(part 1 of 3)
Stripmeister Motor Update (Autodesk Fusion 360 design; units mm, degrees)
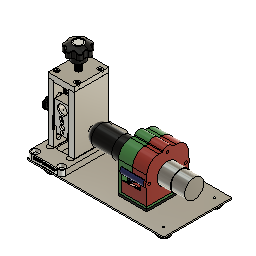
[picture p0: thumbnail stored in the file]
sketch "Sketch1" plane through (0, 0, 0) normal (0, 0, 1) x axis (1, 0, 0)
  line L1 (-38.1, -74.8109) -> (38.1, -74.8109)
  line L2 (-38.1, 74.8109) -> (-38.1, -74.8109)
  line L3 (38.1, 74.8109) -> (-38.1, 74.8109)
  line L4 (38.1, -74.8109) -> (38.1, 74.8109)
  line L5 (-38.1, 74.8109) -> (38.1, -74.8109)
  line L6 (38.1, 74.8109) -> (-38.1, -74.8109)
  line L7 (0, -74.8109) -> (0, 74.8109)
  line L8 (22.225, -74.8109) -> (22.225, 74.8109)
  line L9 (22.225, 0) -> (0, 0)
  line L10 (15.621, -39.4335) -> (15.621, 39.4335)
  line L11 (28.829, 39.4335) -> (28.829, -39.4335)
  line L12 (22.225, -46.0375) -> (22.225, 46.0375)
  line L13 (16.6687, -29.3687) -> (16.6688, 29.3687)
  line L14 (27.7813, 29.3687) -> (27.7813, -29.3688)
  line L15 (22.225, -34.925) -> (22.225, 34.925)
  line L16 (-28.829, 39.4335) -> (-28.829, -39.4335)
  line L17 (-27.7813, 29.3688) -> (-27.7813, -29.3688)
  line L18 (-16.6687, -29.3687) -> (-16.6688, 29.3687)
  line L19 (-15.621, -39.4335) -> (-15.621, 39.4335)
  line L20 (-12.7, 4.1513) -> (12.7, 4.1513)
  line L21 (-12.7, -37.5047) -> (-12.7, 4.1513)
  line L22 (12.7, -37.5047) -> (-12.7, -37.5047)
  line L23 (12.7, 4.1513) -> (12.7, -37.5047)
  line L24 (-12.7, -37.5047) -> (12.7, 4.1513)
  line L25 (12.7, -37.5047) -> (-12.7, 4.1513)
  line L26 (5.08, 10.8982) -> (0, 10.8982)
  line L27 (-3.175, 8.5169) -> (3.175, 8.5169)
  line L28 (-6.35, 18.0419) -> (-6.35, 11.6919)
  line L29 (3.175, 21.2169) -> (-3.175, 21.2169)
  line L30 (6.35, 11.6919) -> (6.35, 18.0419)
  line L31 (-6.35, 21.2169) -> (6.35, 8.5169)
  line L32 (6.35, 21.2169) -> (-6.35, 8.5169)
  circle C1 centre (22.225, 25.4) radius 3.9687
  circle C2 centre (22.225, -25.4) radius 3.9687
  circle C3 centre (-22.225, 25.4) radius 3.9687
  circle C4 centre (-22.225, -25.4) radius 3.9687
  arc A1 centre (22.225, -39.4335) radius 6.604 clockwise from (28.829, -39.4335) to (15.621, -39.4335)
  arc A2 centre (22.225, 39.4335) radius 6.604 clockwise from (15.621, 39.4335) to (28.829, 39.4335)
  arc A3 centre (22.225, -29.3688) radius 5.5563 clockwise from (27.7813, -29.3688) to (16.6687, -29.3687)
  arc A4 centre (22.225, 29.3687) radius 5.5563 clockwise from (16.6688, 29.3687) to (27.7813, 29.3687)
  arc A5 centre (-22.225, 39.4335) radius 6.604 clockwise from (-28.829, 39.4335) to (-15.621, 39.4335)
  arc A6 centre (-22.225, 29.3687) radius 5.5562 clockwise from (-27.7813, 29.3688) to (-16.6688, 29.3687)
  arc A7 centre (-22.225, -39.4335) radius 6.604 clockwise from (-15.621, -39.4335) to (-28.829, -39.4335)
  arc A8 centre (-22.225, -29.3688) radius 5.5562 clockwise from (-16.6687, -29.3687) to (-27.7813, -29.3688)
  circle C5 centre (-22.225, -25.4) radius 3.9687
  circle C6 centre (-22.225, 25.4) radius 3.9687
  circle C7 centre (28.575, 65.2859) radius 4.7625
  circle C8 centre (-28.575, 65.2859) radius 4.7625
  circle C9 centre (28.575, -65.2859) radius 3.9687
  circle C10 centre (-28.575, -65.2859) radius 3.9687
  circle C11 centre (0, 14.8669) radius 3.9688
  arc A9 centre (3.175, 11.6919) radius 3.175 clockwise from (6.35, 11.6919) to (3.175, 8.5169)
  arc A10 centre (-3.175, 11.6919) radius 3.175 clockwise from (-3.175, 8.5169) to (-6.35, 11.6919)
  arc A11 centre (-3.175, 18.0419) radius 3.175 clockwise from (-6.35, 18.0419) to (-3.175, 21.2169)
  arc A12 centre (3.175, 18.0419) radius 3.175 clockwise from (3.175, 21.2169) to (6.35, 18.0419)
  circle C12 centre (0, 62.4919) radius 3.9687
  point P6 (0, 0)
  point P1 (0, 0)
  point P7 (0, 74.8109)
  point P8 (0, -74.8109)
  point P9 (22.225, 74.8109)
  point P10 (22.225, -74.8109)
  point P11 (22.225, 25.4)
  point P12 (22.225, -25.4)
  point P13 (0, 0)
  point P14 (22.225, 0)
  point P23 (22.225, 46.0375)
  point P24 (22.225, -46.0375)
  point P31 (22.225, 34.925)
  point P32 (22.225, -34.925)
  point P17 (15.621, 39.4335)
  point P35 (-15.621, 39.4335)
  point P18 (15.621, -39.4335)
  point P42 (-15.621, -39.4335)
  point P19 (28.829, -39.4335)
  point P36 (-28.829, -39.4335)
  point P20 (28.829, 39.4335)
  point P34 (-28.829, 39.4335)
  point P25 (16.6688, 29.3687)
  point P40 (-16.6688, 29.3687)
  point P26 (16.6687, -29.3687)
  point P41 (-16.6687, -29.3687)
  point P27 (27.7813, -29.3688)
  point P37 (-27.7813, -29.3688)
  point P28 (27.7813, 29.3687)
  point P38 (-27.7813, 29.3688)
  point P51 (0, -16.6767)
  point P56 (0, 10.8982)
  point P58 (0, 14.8669)
  point P63 (0, 14.8669)
  point P59 (6.35, 8.5169)
  point P60 (-6.35, 8.5169)
  point P61 (-6.35, 21.2169)
  point P62 (6.35, 21.2169)
  point P76 (0, 62.4919)
  point P4 (-38.1, 74.8109)
  point P5 (38.1, 74.8109)
  point P3 (-38.1, -74.8109)
  point P49 (-12.7, -37.5047)
  point P50 (12.7, -37.5047)
  point P48 (-12.7, 4.1513)
  point P54 (28.575, -65.2859)
  point P52 (28.575, 65.2859)
  horizontal L1
  perpendicular L1 L2
  parallel L1 L3
  parallel L2 L4
  coincident L5 P6
  coincident L6 P6
  coincident P1 P6
  midpoint L3 P7
  midpoint L1 P8
  coincident L3 P9
  coincident L1 P10
  perpendicular L1 L8
  coincident L8 P11
  coincident L8 P12
  coincident P1 P13
  midpoint L8 P14
  symmetric L7 C1 C3
  symmetric L7 C2 C4
  tangent L10 A1
  tangent A1 L11
  parallel L10 L11
  tangent L11 A2
  tangent L10 A2
  midpoint A2 P23
  midpoint A1 P24
  coincident L8 P24
  parallel L8 L12
  midpoint P14 L12
  tangent L13 A3
  tangent A3 L14
  parallel L13 L14
  tangent L14 A4
  tangent L13 A4
  midpoint A4 P31
  midpoint A3 P32
  parallel L12 L15
  coincident L12 P31
  midpoint P14 L15
  symmetric L7 C1 C6
  symmetric L7 C2 C5
  symmetric L7 P17 P35
  symmetric L7 P18 P42
  symmetric L7 P19 P36
  symmetric L7 P20 P34
  symmetric L7 A1 A7
  symmetric L7 A2 A5
  symmetric L7 P25 P40
  symmetric L7 P26 P41
  symmetric L7 P27 P37
  symmetric L7 P28 P38
  symmetric L7 A3 A8
  symmetric L7 A4 A6
  horizontal L20
  perpendicular L20 L21
  parallel L20 L22
  parallel L21 L23
  coincident L24 P51
  coincident L25 P51
  coincident L7 P51
  symmetric L7 C7 C8
  symmetric L7 C9 C10
  coincident L7 P56
  perpendicular L7 L26
  coincident L7 P58
  tangent L26 C11
  horizontal L27
  perpendicular L27 L28
  parallel L27 L29
  parallel L28 L30
  coincident L31 P63
  coincident L32 P63
  coincident P58 P63
  coincident P59 L30
  coincident P59 L27
  tangent L30 A9
  tangent L27 A9
  coincident P60 L27
  coincident P60 L28
  tangent L27 A10
  tangent L28 A10
  equal A9 A10
  coincident P61 L28
  coincident P61 L29
  tangent L28 A11
  tangent L29 A11
  equal A9 A11
  coincident P62 L29
  coincident P62 L30
  tangent L29 A12
  tangent L30 A12
  equal A9 A12
  coincident L7 P76
  dimension "d1" distance P4 P5 = 76.2
  dimension "d2" distance P3 P4 = 149.6219 (= "5 57/64")
  dimension "d3" diameter C1 = 7.9375 (= "( 5 / 16 ) * 1 in")
  dimension "d4" diameter C2 = 7.9375 (= "( 5 / 16 ) * 1 in")
  dimension "d5" distance P11 L9 = 25.4
  dimension "d6" distance P12 L9 = 25.4
  dimension "d7" distance L7 P11 = 22.225 (= "( 1.75 / 2 ) * 1 in")
  dimension "d8" diameter A1 = 13.208
  dimension "d9" distance P23 P24 = 92.075
  dimension "d10" distance P31 P32 = 69.85
  dimension "d11" diameter A3 = 11.1125
  dimension "d12" distance P49 P50 = 25.4
  dimension "d13" distance P48 P49 = 41.656
  dimension "d14" distance L1 L22 = 37.3062 (= "1 15/32")
  dimension "d16" diameter C7 = 9.525 (= "( 3 / 8 ) * 1 in")
  dimension "d17" diameter C9 = 7.9375
  dimension "d18" distance L4 P54 = 9.525 (= "( 3 / 8 ) * 1 in")
  dimension "d19" distance L1 P54 = 9.525 (= "( 3 / 8 ) * 1 in")
  dimension "d20" distance L3 P52 = 9.525 (= "( 3 / 8 ) * 1 in")
  dimension "d21" distance L4 P52 = 9.525 (= "( 3 / 8 ) * 1 in")
  dimension "d22" distance L20 L26 = 6.7469 (= "( 17 / 64 ) * 1 in")
  dimension "d23" diameter C11 = 7.9375 (= "( 5 / 16 ) * 1 in")
  dimension "d24" distance P61 P62 = 12.7
  dimension "d25" distance P60 P61 = 12.7
  dimension "d26" radius A9 = 3.175
  dimension "d27" diameter C12 = 7.9375 (= "( 5 / 16 ) * 1 in")
  dimension "d28" distance P58 P76 = 47.625 (= "1 7/8")
extrude "Extrude1" new body sketch "Sketch1" profile of L1 L2 L3 L4 C1 C2 C3 C4 L10 A1 L11 A2 L13 A3 L14 A4 A5 L16 L17 A6 L18 L19 A7 A8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 against normal blind 12.7
extrude "Extrude2" cut sketch "Sketch1" profile of C1 C2 C3 C4 L13 A3 L14 A4 L17 A6 L18 A8 C5 C6 against normal blind 2.3813 (magnitude of "( -3 / 32 ) * 1 in")
extrude "Extrude3" cut sketch "Sketch1" profile of L10 A1 L11 A2 L13 A3 L14 A4 A5 L16 L17 A6 L18 L19 A7 A8 against normal blind 0.3969 (magnitude of "( -1 / 64 ) * 1 in")
chamfer "Chamfer1" distance 3.81
extrude "Extrude4" cut sketch "Sketch1" profile of C11 L27 L28 L29 L30 A9 A10 A11 A12 against normal blind 4.3656 (magnitude of "( -11 / 64 ) * 1 in")
fillet "Fillet1" radius 7.9375 (= "( 5 / 16 ) * 1 in")
fillet "Fillet2" radius 4.7625
sketch "Sketch1" plane through (0, 0, 0) normal (0, 0, 1) x axis (-1, 0, 0)
  line L1 (-6.35, -11.6919) -> (-6.35, -18.0419)
  line L2 (3.175, -8.5169) -> (-3.175, -8.5169)
  line L3 (6.35, -18.0419) -> (6.35, -11.6919)
  line L4 (-3.175, -21.2169) -> (3.175, -21.2169)
  line L5 (38.1, 66.8734) -> (38.1, -66.8734)
  line L6 (-30.1625, 74.8109) -> (30.1625, 74.8109)
  line L7 (-38.1, -66.8734) -> (-38.1, 66.8734)
  line L8 (30.1625, -74.8109) -> (-30.1625, -74.8109)
  line L9 (-12.7, 32.7422) -> (-12.7, 0.6112)
  line L10 (7.9375, 37.5047) -> (-7.9375, 37.5047)
  line L11 (12.7, 0.6112) -> (12.7, 32.7422)
  line L12 (-7.9375, -4.1513) -> (7.9375, -4.1513)
  line L13 (-15.621, -39.4335) -> (-15.621, 39.4335)
  line L14 (-28.829, 39.4335) -> (-28.829, -39.4335)
  line L15 (28.829, -39.4335) -> (28.829, 39.4335)
  line L16 (15.621, 39.4335) -> (15.621, -39.4335)
  line L17 (-6.35, -18.0419) -> (-6.35, -11.6919)
  line L18 (3.175, -21.2169) -> (-3.175, -21.2169)
  line L19 (6.35, -11.6919) -> (6.35, -18.0419)
  line L20 (-3.175, -8.5169) -> (3.175, -8.5169)
  arc A1 centre (-3.175, -11.6919) radius 3.175 clockwise from (-6.35, -11.6919) to (-3.175, -8.5169)
  arc A2 centre (3.175, -11.6919) radius 3.175 clockwise from (3.175, -8.5169) to (6.35, -11.6919)
  arc A3 centre (3.175, -18.0419) radius 3.175 clockwise from (6.35, -18.0419) to (3.175, -21.2169)
  arc A4 centre (-3.175, -18.0419) radius 3.175 clockwise from (-3.175, -21.2169) to (-6.35, -18.0419)
  circle C1 centre (-28.575, 65.2859) radius 7.7787
  arc A5 centre (30.1625, -66.8734) radius 7.9375 clockwise from (38.1, -66.8734) to (30.1625, -74.8109)
  arc A6 centre (30.1625, 66.8734) radius 7.9375 clockwise from (30.1625, 74.8109) to (38.1, 66.8734)
  arc A7 centre (-30.1625, 66.8734) radius 7.9375 clockwise from (-38.1, 66.8734) to (-30.1625, 74.8109)
  arc A8 centre (-30.1625, -66.8734) radius 7.9375 clockwise from (-30.1625, -74.8109) to (-38.1, -66.8734)
  arc A9 centre (-7.9375, 32.7422) radius 4.7625 clockwise from (-12.7, 32.7422) to (-7.9375, 37.5047)
  arc A10 centre (7.9375, 32.7422) radius 4.7625 clockwise from (7.9375, 37.5047) to (12.7, 32.7422)
  arc A11 centre (7.9375, 0.6112) radius 4.7625 clockwise from (12.7, 0.6112) to (7.9375, -4.1513)
  arc A12 centre (-7.9375, 0.6112) radius 4.7625 clockwise from (-7.9375, -4.1513) to (-12.7, 0.6112)
  arc A13 centre (-22.225, -39.4335) radius 6.604 clockwise from (-15.621, -39.4335) to (-28.829, -39.4335)
  arc A14 centre (-22.225, 39.4335) radius 6.604 clockwise from (-28.829, 39.4335) to (-15.621, 39.4335)
  arc A15 centre (22.225, -39.4335) radius 6.604 clockwise from (28.829, -39.4335) to (15.621, -39.4335)
  arc A16 centre (22.225, 39.4335) radius 6.604 clockwise from (15.621, 39.4335) to (28.829, 39.4335)
  circle C2 centre (0, -62.4919) radius 7.7787
  circle C3 centre (28.575, 65.2859) radius 7.7787
  circle C4 centre (0, -14.8669) radius 3.9687
  arc A17 centre (-3.175, -11.6919) radius 3.175 clockwise from (-6.35, -11.6919) to (-3.175, -8.5169)
  arc A18 centre (-3.175, -18.0419) radius 3.175 clockwise from (-3.175, -21.2169) to (-6.35, -18.0419)
  arc A19 centre (3.175, -18.0419) radius 3.175 clockwise from (6.35, -18.0419) to (3.175, -21.2169)
  arc A20 centre (3.175, -11.6919) radius 3.175 clockwise from (3.175, -8.5169) to (6.35, -11.6919)
  circle C5 centre (0, -14.8669) radius 9.3266
  concentric C4 C5
  dimension "d42" diameter C5 = 18.6531 (= "( 47 / 64 ) * 1 in")
extrude "Extrude1" new body sketch "Sketch1" profile of L1 A1 L2 A2 L3 A3 L4 A4 C4 A17 L17 A18 L18 A19 L19 A20 L20 to an object
extrude "Extrude2" add sketch "Sketch1" profile of L1 A1 L2 A2 L3 A3 L4 A4 C4 A17 L17 A18 L18 A19 L19 A20 L20 C5 along normal blind 38.608
extrude "Extrude3" add sketch "Sketch1" profile of C4 against normal blind 4.3688
extrude "Extrude4" cut of existing geometry blind 0
extrude "Extrude5" add sketch "Sketch1" profile of L1 A1 L2 A2 L3 A3 L4 A4 C4 A17 L17 A18 L18 A19 L19 A20 L20 against normal blind 4.3688
extrude "Extrude6" sketch "Sketch1" profile of C4 blind 15.875 (= "( 5 / 8 ) * 1 in")
sketch "Sketch2" plane through (0, 0, 38.608) normal (0, 0, 1) x axis (-1, 0, 0)
  line L1 (-9.144, -16.7032) -> (9.144, -16.7032)
  line L2 (0, -5.5404) -> (0, -16.7032)
  circle C1 centre (0, -14.8669) radius 9.3266
  arc A1 centre (-16.0599, -1.7116) radius 16.51 clockwise from (0, -5.5404) to (-9.144, -16.7032)
  arc A2 centre (16.0599, -1.7116) radius 16.51 clockwise from (9.144, -16.7032) to (0, -5.5404)
  point P3 (9.144, -16.7032)
  point P4 (-9.144, -16.7032)
  point P5 (0, -16.7032)
  point P6 (0, -5.5404)
  point P9 (9.144, -16.7032)
  point P10 (0, -5.5404)
  coincident C1 P3
  coincident C1 P4
  horizontal L1
  midpoint L1 P5
  coincident C1 P6
  perpendicular L1 L2
  symmetric P4 L2 P9
  symmetric P6 L2 P10
  symmetric L2 A1 A2
  dimension "d57" distance P3 P4 = 18.288
  dimension "d58" radius A1 = 16.51
extrude "Extrude7" cut sketch "Sketch2" profile of C1 A1 A2 against normal blind 12.7
sketch "Sketch3" plane through (0, 0, 38.608) normal (0, 0, 1) x axis (-1, 0, 0)
  arc A1 centre (16.0599, -1.7116) radius 16.51 clockwise from (9.144, -16.7032) to (0, -5.5404)
  arc A2 centre (-16.0599, -1.7116) radius 16.51 clockwise from (0, -5.5404) to (-9.144, -16.7032)
  arc A3 centre (0, -14.8669) radius 9.3266 clockwise from (9.144, -16.7032) to (-9.144, -16.7032)
  arc A4 centre (0, -14.8669) radius 9.3266 clockwise from (9.144, -16.7032) to (-9.144, -16.7032)
  arc A5 centre (0, -14.8669) radius 9.3266 clockwise from (-9.144, -16.7032) to (0, -5.5404)
  arc A6 centre (0, -14.8669) radius 9.3266 clockwise from (0, -5.5404) to (9.144, -16.7032)
  circle C1 centre (0, -14.8669) radius 9.3266
  arc A7 centre (0, -14.8669) radius 9.1996 clockwise from (9.0195, -16.6782) to (-9.0195, -16.6782)
  arc A8 centre (0, -14.8669) radius 9.1996 clockwise from (0, -5.6674) to (9.0195, -16.6782)
  arc A9 centre (0, -14.8669) radius 9.1996 clockwise from (-9.0195, -16.6782) to (0, -5.6674)
  dimension "d61" = -0.127
extrude "Extrude8" cut sketch "Sketch3" blind -0.635 from offset -20.9677
fillet "Fillet1" radius 0.254
thread "Thread1"
sketch "Sketch2" plane through (0, 0, -12.7) normal (0, 0, -1) x axis (1, 0, 0)
  line L1 (30.1625, -74.8109) -> (-30.1625, -74.8109)
  line L2 (38.1, 66.8734) -> (38.1, -66.8734)
  line L3 (-30.1625, 74.8109) -> (30.1625, 74.8109)
  line L4 (-38.1, -66.8734) -> (-38.1, 66.8734)
  line L5 (12.7, 0.6112) -> (12.7, 32.7422)
  line L6 (-7.9375, -4.1513) -> (7.9375, -4.1513)
  line L7 (-12.7, 32.7422) -> (-12.7, 0.6112)
  line L8 (7.9375, 37.5047) -> (-7.9375, 37.5047)
  arc A1 centre (-30.1625, -66.8734) radius 7.9375 clockwise from (-30.1625, -74.8109) to (-38.1, -66.8734)
  arc A2 centre (30.1625, -66.8734) radius 7.9375 clockwise from (38.1, -66.8734) to (30.1625, -74.8109)
  arc A3 centre (30.1625, 66.8734) radius 7.9375 clockwise from (30.1625, 74.8109) to (38.1, 66.8734)
  arc A4 centre (-30.1625, 66.8734) radius 7.9375 clockwise from (-38.1, 66.8734) to (-30.1625, 74.8109)
  circle C1 centre (-22.225, -25.4) radius 3.9687
  circle C2 centre (28.575, 65.2859) radius 3.9687
  circle C3 centre (-22.225, 25.4) radius 3.9687
  circle C4 centre (0, -14.8669) radius 3.9687
  circle C5 centre (-28.575, 65.2859) radius 3.9687
  circle C6 centre (0, -62.4919) radius 3.9687
  circle C7 centre (22.225, -25.4) radius 3.9688
  circle C8 centre (22.225, 25.4) radius 3.9687
  arc A5 centre (7.9375, 0.6112) radius 4.7625 clockwise from (12.7, 0.6112) to (7.9375, -4.1513)
  arc A6 centre (-7.9375, 0.6112) radius 4.7625 clockwise from (-7.9375, -4.1513) to (-12.7, 0.6112)
  arc A7 centre (-7.9375, 32.7422) radius 4.7625 clockwise from (-12.7, 32.7422) to (-7.9375, 37.5047)
  arc A8 centre (7.9375, 32.7422) radius 4.7625 clockwise from (7.9375, 37.5047) to (12.7, 32.7422)
  circle C9 centre (22.225, 25.4) radius 5.1594
  circle C10 centre (22.225, -25.4) radius 5.1594
  circle C11 centre (-22.225, -25.4) radius 5.1594
  circle C12 centre (-22.225, 25.4) radius 5.1594
  circle C13 centre (0, -14.8669) radius 5.1594
  concentric C8 C9
  concentric C7 C10
  concentric C1 C11
  concentric C3 C12
  concentric C4 C13
  dimension "d67" diameter C9 = 10.3188 (= "( 13 / 32 ) * 1 in")
  dimension "d68" diameter C10 = 10.3188 (= "( 13 / 32 ) * 1 in")
  dimension "d69" diameter C11 = 10.3188 (= "( 13 / 32 ) * 1 in")
  dimension "d70" diameter C12 = 10.3188 (= "( 13 / 32 ) * 1 in")
  dimension "d71" diameter C13 = 10.3188 (= "( 13 / 32 ) * 1 in")
extrude "Extrude5" cut sketch "Sketch2" profile of C1 C3 C4 C7 C8 C9 C10 C11 C12 C13 against normal blind 4.7625 (magnitude of "( -3 / 16 ) * 1 in")
base_feature "Base Feature1"
position "Position1"
copy_paste_bodies "CopyPasteBodies1"
move "Move1"
copy_paste_bodies "CopyPasteBodies2"
move "Move2"
copy_paste_bodies "CopyPasteBodies3"
move "Move3"
align "Align1"
align "Align2"
align "Align3"
align "Align4"
sketch "Sketch1" plane through (0, 0, 0) normal (0, 0, 1) x axis (-1, 0, 0)
  line L1 (-6.35, -11.6919) -> (-6.35, -18.0419)
  line L2 (3.175, -8.5169) -> (-3.175, -8.5169)
  line L3 (6.35, -18.0419) -> (6.35, -11.6919)
  line L4 (-3.175, -21.2169) -> (3.175, -21.2169)
  line L5 (38.1, 66.8734) -> (38.1, -66.8734)
  line L6 (-30.1625, 74.8109) -> (30.1625, 74.8109)
  line L7 (-38.1, -66.8734) -> (-38.1, 66.8734)
  line L8 (30.1625, -74.8109) -> (-30.1625, -74.8109)
  line L9 (-12.7, 32.7422) -> (-12.7, 0.6112)
  line L10 (7.9375, 37.5047) -> (-7.9375, 37.5047)
  line L11 (12.7, 0.6112) -> (12.7, 32.7422)
  line L12 (-7.9375, -4.1513) -> (7.9375, -4.1513)
  line L13 (-15.621, -39.4335) -> (-15.621, 39.4335)
  line L14 (-28.829, 39.4335) -> (-28.829, -39.4335)
  line L15 (28.829, -39.4335) -> (28.829, 39.4335)
  line L16 (15.621, 39.4335) -> (15.621, -39.4335)
  line L17 (27.7813, 29.3688) -> (27.7813, -29.3687)
  line L18 (16.6688, -29.3687) -> (16.6688, 29.3687)
  line L19 (22.225, -25.4) -> (22.225, 25.4)
  line L20 (15.875, -38.1) -> (28.575, -38.1)
  line L21 (15.875, 38.1) -> (15.875, -38.1)
  line L22 (28.575, 38.1) -> (15.875, 38.1)
  line L23 (28.575, -38.1) -> (28.575, 38.1)
  line L24 (15.875, 38.1) -> (28.575, -38.1)
  line L25 (28.575, 38.1) -> (15.875, -38.1)
  arc A1 centre (-3.175, -11.6919) radius 3.175 clockwise from (-6.35, -11.6919) to (-3.175, -8.5169)
  arc A2 centre (3.175, -11.6919) radius 3.175 clockwise from (3.175, -8.5169) to (6.35, -11.6919)
  arc A3 centre (3.175, -18.0419) radius 3.175 clockwise from (6.35, -18.0419) to (3.175, -21.2169)
  arc A4 centre (-3.175, -18.0419) radius 3.175 clockwise from (-3.175, -21.2169) to (-6.35, -18.0419)
  circle C1 centre (-28.575, 65.2859) radius 7.7787
  arc A5 centre (30.1625, -66.8734) radius 7.9375 clockwise from (38.1, -66.8734) to (30.1625, -74.8109)
  arc A6 centre (30.1625, 66.8734) radius 7.9375 clockwise from (30.1625, 74.8109) to (38.1, 66.8734)
  arc A7 centre (-30.1625, 66.8734) radius 7.9375 clockwise from (-38.1, 66.8734) to (-30.1625, 74.8109)
  arc A8 centre (-30.1625, -66.8734) radius 7.9375 clockwise from (-30.1625, -74.8109) to (-38.1, -66.8734)
  arc A9 centre (-7.9375, 32.7422) radius 4.7625 clockwise from (-12.7, 32.7422) to (-7.9375, 37.5047)
  arc A10 centre (7.9375, 32.7422) radius 4.7625 clockwise from (7.9375, 37.5047) to (12.7, 32.7422)
  arc A11 centre (7.9375, 0.6112) radius 4.7625 clockwise from (12.7, 0.6112) to (7.9375, -4.1513)
  arc A12 centre (-7.9375, 0.6112) radius 4.7625 clockwise from (-7.9375, -4.1513) to (-12.7, 0.6112)
  arc A13 centre (-22.225, -39.4335) radius 6.604 clockwise from (-15.621, -39.4335) to (-28.829, -39.4335)
  arc A14 centre (-22.225, 39.4335) radius 6.604 clockwise from (-28.829, 39.4335) to (-15.621, 39.4335)
  arc A15 centre (22.225, -39.4335) radius 6.604 clockwise from (28.829, -39.4335) to (15.621, -39.4335)
  arc A16 centre (22.225, 39.4335) radius 6.604 clockwise from (15.621, 39.4335) to (28.829, 39.4335)
  circle C2 centre (0, -62.4919) radius 7.7787
  circle C3 centre (28.575, 65.2859) radius 7.7787
  circle C4 centre (22.225, -25.4) radius 3.9687
  circle C5 centre (22.225, 25.4) radius 3.9687
  arc A17 centre (22.225, -29.3687) radius 5.5562 clockwise from (27.7813, -29.3687) to (16.6688, -29.3687)
  arc A18 centre (22.225, 29.3688) radius 5.5562 clockwise from (16.6688, 29.3687) to (27.7813, 29.3688)
  point P54 (22.225, 25.4)
  point P61 (22.225, 25.4)
  point P53 (22.225, -25.4)
  point P62 (22.225, -25.4)
  point P67 (22.225, 0)
  point P65 (15.875, 38.1)
  point P66 (28.575, 38.1)
  point P64 (15.875, -38.1)
  coincident P54 P61
  coincident P53 P62
  horizontal L20
  perpendicular L20 L21
  parallel L20 L22
  parallel L21 L23
  coincident L24 P67
  coincident L25 P67
  midpoint L19 P67
  dimension "d74" distance P65 P66 = 12.7
  dimension "d75" distance P64 P65 = 76.2
extrude "Extrude1" new body sketch "Sketch1" profile of C4 C5 A17 L17 A18 L18 to an object
extrude "Extrude2" add sketch "Sketch1" profile of C4 C5 A17 L17 A18 L18 L20 L21 L22 L23 along normal blind 127
extrude "Extrude3" cut sketch "Sketch1" profile of C4 C5 along normal blind 16.129
sketch "Sketch2" plane through (0, 0, 127) normal (0, 0, 1) x axis (-1, 0, 0)
  line L1 (15.875, 38.1) -> (28.575, 38.1)
  line L2 (15.875, -38.1) -> (15.875, 38.1)
  line L3 (28.575, -38.1) -> (15.875, -38.1)
  line L4 (28.575, 38.1) -> (28.575, -38.1)
  circle C1 centre (22.225, 25.4) radius 3.9687
  circle C2 centre (22.225, -25.4) radius 3.9687
  circle C3 centre (22.225, -25.4) radius 5.5245
  circle C4 centre (22.225, 25.4) radius 5.5245
  concentric C2 C3
  concentric C1 C4
  dimension "d83" diameter C3 = 11.049
  dimension "d84" diameter C4 = 11.049
extrude "Extrude4" add sketch "Sketch2" profile of C1 C2 C3 C4 along normal blind 1.778
extrude "Extrude5" of existing geometry blind -16.129
thread "Thread1"
fillet "Fillet1" radius 1.27
align "Align1"
sketch "Sketch3" plane through (15.875, 0, 0) normal (-1, 0, 0) x axis (0, -1, 0)
  line L1 (38.1, 0) -> (-38.1, 0)
  line L2 (38.1, 127) -> (38.1, 0)
  line L3 (-38.1, 127) -> (38.1, 127)
  line L4 (-38.1, 0) -> (-38.1, 127)
  line L5 (20.574, 15.748) -> (20.574, 93.472)
  line L6 (31.75, 93.472) -> (31.75, 15.748)
  line L7 (26.162, 10.16) -> (26.162, 99.06)
  line L8 (38.1, 52.6923) -> (-38.1, 52.6923)
  line L9 (0, 52.6923) -> (0, 127)
  line L10 (5.588, 58.2803) -> (0, 58.2803)
  line L11 (-5.588, 58.2803) -> (0, 58.2803)
  line L12 (-5.588, 127) -> (-5.588, 58.2803)
  line L13 (5.588, 127) -> (5.588, 58.2803)
  line L14 (6.096, 127) -> (-6.096, 127)
  line L15 (5.588, 116.84) -> (-5.588, 116.84)
  line L16 (-5.588, 116.84) -> (-6.096, 127)
  line L17 (5.588, 116.84) -> (6.096, 127)
  line L18 (0, 0) -> (0, 58.2803)
  line L19 (0, 10.16) -> (38.1, 10.16)
  arc A1 centre (26.162, 15.748) radius 5.588 clockwise from (31.75, 15.748) to (20.574, 15.748)
  arc A2 centre (26.162, 93.472) radius 5.588 clockwise from (20.574, 93.472) to (31.75, 93.472)
  circle C1 centre (0, 58.2803) radius 5.588
  circle C2 centre (0, 38.1) radius 11.43
  circle C3 centre (0, 38.1) radius 5.8674
  point P12 (26.162, 99.06)
  point P13 (26.162, 10.16)
  point P14 (-38.1, 52.6923)
  point P15 (38.1, 52.6923)
  point P16 (0, 127)
  point P17 (0, 52.6923)
  point P18 (0, 58.2803)
  point P19 (0, 58.2803)
  point P20 (5.588, 58.2803)
  point P21 (0, 58.2803)
  point P22 (-5.588, 58.2803)
  point P23 (-5.588, 127)
  point P24 (5.588, 127)
  point P27 (-5.588, 116.84)
  point P28 (5.588, 116.84)
  point P29 (0, 58.2803)
  point P1 (0, 0)
  point P30 (0, 0)
  point P31 (0, 38.1)
  point P32 (38.1, 10.16)
  point P33 (0, 10.16)
  point P25 (-6.096, 127)
  point P26 (6.096, 127)
  tangent L5 A1
  tangent A1 L6
  parallel L5 L6
  tangent L6 A2
  tangent L5 A2
  midpoint A2 P12
  midpoint A1 P13
  parallel L2 L7
  coincident L4 P14
  coincident L2 P15
  perpendicular L2 L8
  midpoint L3 P16
  midpoint L8 P17
  coincident L9 P18
  tangent L8 C1
  coincident P18 P19
  coincident C1 P20
  perpendicular L9 L10
  coincident P18 P21
  coincident C1 P22
  perpendicular L9 L11
  coincident L3 P23
  tangent C1 L12
  coincident L3 P24
  tangent C1 L13
  perpendicular L13 L14
  midpoint P16 L14
  coincident L12 P27
  coincident L13 P28
  perpendicular L13 L15
  coincident P18 P29
  coincident P1 P30
  coincident L18 P31
  coincident L2 P32
  coincident L18 P33
  perpendicular L18 L19
  tangent A1 L19
  concentric C2 C3
  dimension "d92" diameter A1 = 11.176
  dimension "d93" distance L3 L8 = 74.3077
  dimension "d94" diameter C1 = 11.176
  dimension "d95" distance P25 P26 = 12.192
  dimension "d96" distance L14 L15 = 10.16
  dimension "d97" distance P1 P31 = 38.1
  dimension "d98" diameter C2 = 22.86
  dimension "d99" distance L2 L6 = 6.35
  dimension "d100" distance L1 L19 = 10.16
  dimension "d101" diameter C3 = 11.7348
extrude "Extrude6" cut sketch "Sketch3" profile of L3 L5 A1 L6 A2 C1 L12 L13 L16 L17 against normal blind 3.175 (magnitude of "( -1 / 8 ) * 1 in")
extrude "Extrude7" cut sketch "Sketch3" profile of C3 against normal blind 12.7
extrude "Extrude8" cut sketch "Sketch3" profile of C2 C3 against normal blind 7.9375
fillet "Fillet2" radius 1.27
mirror "Mirror1" mirrorStitchTolerance 0.1016
copy_paste_bodies "CutPasteBodies"
component_from_bodies "Body->Comp"
delete_face "DeleteFace1"
base_feature "Base Feature1"
offset_faces "OffsetFaces1" distance 0.381
base_feature "Base Feature1"
position "Position2"
position "Position3"
sketch "Sketch1" plane through (-15.875, 0, 0) normal (1, 0, 0) x axis (0, 1, 0)
  line L1 (5.588, 116.84) -> (6.0357, 125.7934)
  line L2 (5.588, 58.2803) -> (5.588, 116.84)
  line L3 (-5.588, 116.84) -> (-5.588, 58.2803)
  line L4 (-6.0357, 125.7934) -> (-5.588, 116.84)
  line L5 (-38.1, 127) -> (-7.3041, 127)
  line L6 (-38.1, 0) -> (-38.1, 127)
  line L7 (38.1, 0) -> (-38.1, 0)
  line L8 (38.1, 127) -> (38.1, 0)
  line L9 (7.3041, 127) -> (38.1, 127)
  line L10 (-20.574, 15.748) -> (-20.574, 93.472)
  line L11 (-31.75, 93.472) -> (-31.75, 15.748)
  line L12 (-11.475, 113.75) -> (-16.725, 113.75)
  line L13 (-16.725, 114.5) -> (-11.475, 114.5)
  line L14 (-11.1, 114.125) -> (-17.1, 114.125)
  line L15 (-17.1, 114.5) -> (-38.1, 114.5)
  line L16 (-17.1, 127) -> (-17.1, 114.5)
  line L17 (-11.475, 111.6333) -> (-16.725, 111.6333)
  line L18 (-16.725, 112.3833) -> (-11.475, 112.3833)
  line L19 (-11.475, 109.5167) -> (-16.725, 109.5167)
  line L20 (-16.725, 110.2667) -> (-11.475, 110.2667)
  line L21 (-11.475, 107.4) -> (-16.725, 107.4)
  line L22 (-16.725, 108.15) -> (-11.475, 108.15)
  line L23 (-11.475, 105.2833) -> (-16.725, 105.2833)
  line L24 (-16.725, 106.0333) -> (-11.475, 106.0333)
  line L25 (-11.475, 103.1667) -> (-16.725, 103.1667)
  line L26 (-16.725, 103.9167) -> (-11.475, 103.9167)
  line L27 (-11.475, 101.05) -> (-16.725, 101.05)
  line L28 (-16.725, 101.8) -> (-11.475, 101.8)
  line L29 (-11.475, 98.9333) -> (-16.725, 98.9333)
  line L30 (-16.725, 99.6833) -> (-11.475, 99.6833)
  line L31 (-11.475, 96.8167) -> (-16.725, 96.8167)
  line L32 (-16.725, 97.5667) -> (-11.475, 97.5667)
  line L33 (-11.475, 94.7) -> (-16.725, 94.7)
  line L34 (-16.725, 95.45) -> (-11.475, 95.45)
  line L35 (-11.475, 92.5833) -> (-16.725, 92.5833)
  line L36 (-16.725, 93.3333) -> (-11.475, 93.3333)
  line L37 (-11.475, 90.4667) -> (-16.725, 90.4667)
  line L38 (-16.725, 91.2167) -> (-11.475, 91.2167)
  line L39 (-11.475, 88.35) -> (-16.725, 88.35)
  line L40 (-16.725, 89.1) -> (-11.475, 89.1)
  circle C1 centre (0, 38.1) radius 11.049
  arc A1 centre (7.3041, 125.73) radius 1.27 clockwise from (6.0357, 125.7934) to (7.3041, 127)
  arc A2 centre (0, 58.2803) radius 5.588 clockwise from (5.588, 58.2803) to (-5.588, 58.2803)
  arc A3 centre (-7.3041, 125.73) radius 1.27 clockwise from (-7.3041, 127) to (-6.0357, 125.7934)
  arc A4 centre (-26.162, 15.748) radius 5.588 clockwise from (-20.574, 15.748) to (-31.75, 15.748)
  arc A5 centre (-26.162, 93.472) radius 5.588 clockwise from (-31.75, 93.472) to (-20.574, 93.472)
  arc A6 centre (-11.475, 114.125) radius 0.375 clockwise from (-11.475, 114.5) to (-11.475, 113.75)
  arc A7 centre (-16.725, 114.125) radius 0.375 clockwise from (-16.725, 113.75) to (-16.725, 114.5)
  arc A8 centre (-16.725, 112.0083) radius 0.375 clockwise from (-16.725, 111.6333) to (-16.725, 112.3833)
  arc A9 centre (-11.475, 112.0083) radius 0.375 clockwise from (-11.475, 112.3833) to (-11.475, 111.6333)
  arc A10 centre (-16.725, 109.8917) radius 0.375 clockwise from (-16.725, 109.5167) to (-16.725, 110.2667)
  arc A11 centre (-11.475, 109.8917) radius 0.375 clockwise from (-11.475, 110.2667) to (-11.475, 109.5167)
  arc A12 centre (-16.725, 107.775) radius 0.375 clockwise from (-16.725, 107.4) to (-16.725, 108.15)
  arc A13 centre (-11.475, 107.775) radius 0.375 clockwise from (-11.475, 108.15) to (-11.475, 107.4)
  arc A14 centre (-16.725, 105.6583) radius 0.375 clockwise from (-16.725, 105.2833) to (-16.725, 106.0333)
  arc A15 centre (-11.475, 105.6583) radius 0.375 clockwise from (-11.475, 106.0333) to (-11.475, 105.2833)
  arc A16 centre (-16.725, 103.5417) radius 0.375 clockwise from (-16.725, 103.1667) to (-16.725, 103.9167)
  arc A17 centre (-11.475, 103.5417) radius 0.375 clockwise from (-11.475, 103.9167) to (-11.475, 103.1667)
  arc A18 centre (-16.725, 101.425) radius 0.375 clockwise from (-16.725, 101.05) to (-16.725, 101.8)
  arc A19 centre (-11.475, 101.425) radius 0.375 clockwise from (-11.475, 101.8) to (-11.475, 101.05)
  arc A20 centre (-16.725, 99.3083) radius 0.375 clockwise from (-16.725, 98.9333) to (-16.725, 99.6833)
  arc A21 centre (-11.475, 99.3083) radius 0.375 clockwise from (-11.475, 99.6833) to (-11.475, 98.9333)
  arc A22 centre (-16.725, 97.1917) radius 0.375 clockwise from (-16.725, 96.8167) to (-16.725, 97.5667)
  arc A23 centre (-11.475, 97.1917) radius 0.375 clockwise from (-11.475, 97.5667) to (-11.475, 96.8167)
  arc A24 centre (-16.725, 95.075) radius 0.375 clockwise from (-16.725, 94.7) to (-16.725, 95.45)
  arc A25 centre (-11.475, 95.075) radius 0.375 clockwise from (-11.475, 95.45) to (-11.475, 94.7)
  arc A26 centre (-16.725, 92.9583) radius 0.375 clockwise from (-16.725, 92.5833) to (-16.725, 93.3333)
  arc A27 centre (-11.475, 92.9583) radius 0.375 clockwise from (-11.475, 93.3333) to (-11.475, 92.5833)
  arc A28 centre (-16.725, 90.8417) radius 0.375 clockwise from (-16.725, 90.4667) to (-16.725, 91.2167)
  arc A29 centre (-11.475, 90.8417) radius 0.375 clockwise from (-11.475, 91.2167) to (-11.475, 90.4667)
  arc A30 centre (-16.725, 88.725) radius 0.375 clockwise from (-16.725, 88.35) to (-16.725, 89.1)
  arc A31 centre (-11.475, 88.725) radius 0.375 clockwise from (-11.475, 89.1) to (-11.475, 88.35)
  point P30 (-17.1, 114.125)
  point P31 (-11.1, 114.125)
  point P32 (-38.1, 114.5)
  point P34 (-17.1, 127)
  point P33 (-17.1, 114.5)
  tangent L12 A6
  tangent A6 L13
  parallel L12 L13
  tangent L13 A7
  tangent L12 A7
  midpoint A7 P30
  midpoint A6 P31
  horizontal L14
  coincident L6 P32
  perpendicular L6 L15
  coincident L5 P34
  perpendicular L5 L16
  tangent A7 L16
  collinear L13 L15
  dimension "d113" diameter A6 = 0.75
  dimension "d114" distance P32 P33 = 21
  dimension "d115" distance P33 P34 = 12.5
  dimension "d116" distance P30 P31 = 6
  dimension "d119" R-Pattern1-uDistance = 0
  dimension "d120" R-Pattern1-vDistance = -25.4
extrude "Extrude1" cut sketch "Sketch1" profile of L12 A6 L13 A7 A8 L17 L18 A9 A10 L19 L20 A11 A12 L21 L22 A13 A14 L23 L24 A15 A16 L25 L26 A17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 against normal blind 0.25
sketch "Sketch1" plane through (0, 0, 127) normal (0, 0, 1) x axis (-1, 0, 0)
  line L1 (-19.05, 7.3041) -> (-19.05, -7.3041)
  line L2 (-15.875, 7.3041) -> (-19.05, 7.3041)
  line L3 (-15.875, 38.1) -> (-15.875, 7.3041)
  line L4 (-28.575, 38.1) -> (-15.875, 38.1)
  line L5 (-28.575, -38.1) -> (-28.575, 38.1)
  line L6 (-15.875, -38.1) -> (-28.575, -38.1)
  line L7 (-15.875, -7.3041) -> (-15.875, -38.1)
  line L8 (-19.05, -7.3041) -> (-15.875, -7.3041)
  line L9 (-30.1625, -74.8109) -> (30.1625, -74.8109)
  line L10 (-38.1, 66.8734) -> (-38.1, -66.8734)
  line L11 (30.1625, 74.8109) -> (-30.1625, 74.8109)
  line L12 (38.1, -66.8734) -> (38.1, 66.8734)
  line L13 (-12.7, 0.6112) -> (-12.7, 32.7422)
  line L14 (7.9375, -4.1513) -> (-7.9375, -4.1513)
  line L15 (12.7, 32.7422) -> (12.7, 0.6112)
  line L16 (-7.9375, 37.5047) -> (7.9375, 37.5047)
  line L17 (28.575, 38.1) -> (-28.575, 38.1)
  line L18 (28.575, -38.1) -> (28.575, 38.1)
  line L19 (-28.575, -38.1) -> (28.575, -38.1)
  line L20 (-28.575, 38.1) -> (-28.575, -38.1)
  line L21 (-15.875, -38.1) -> (-15.875, 38.1)
  line L22 (15.875, -38.1) -> (15.875, 38.1)
  line L23 (28.575, 0) -> (-28.575, 0)
  line L24 (0, -38.1) -> (0, 38.1)
  circle C1 centre (-22.225, 25.4) radius 5.5245
  circle C2 centre (-22.225, -25.4) radius 5.5245
  circle C3 centre (-22.225, -25.4) radius 5.1594
  circle C4 centre (-22.225, 25.4) radius 5.1594
  circle C5 centre (22.225, -25.4) radius 5.1594
  circle C6 centre (22.225, 25.4) radius 5.1594
  circle C7 centre (0, -14.8669) radius 5.1594
  arc A1 centre (30.1625, -66.8734) radius 7.9375 clockwise from (38.1, -66.8734) to (30.1625, -74.8109)
  arc A2 centre (-30.1625, -66.8734) radius 7.9375 clockwise from (-30.1625, -74.8109) to (-38.1, -66.8734)
  arc A3 centre (-30.1625, 66.8734) radius 7.9375 clockwise from (-38.1, 66.8734) to (-30.1625, 74.8109)
  arc A4 centre (30.1625, 66.8734) radius 7.9375 clockwise from (30.1625, 74.8109) to (38.1, 66.8734)
  circle C8 centre (-28.575, 65.2859) radius 3.9687
  circle C9 centre (28.575, 65.2859) radius 3.9687
  circle C10 centre (0, -62.4919) radius 3.9687
  arc A5 centre (-7.9375, 0.6112) radius 4.7625 clockwise from (-7.9375, -4.1513) to (-12.7, 0.6112)
  arc A6 centre (7.9375, 0.6112) radius 4.7625 clockwise from (12.7, 0.6112) to (7.9375, -4.1513)
  arc A7 centre (7.9375, 32.7422) radius 4.7625 clockwise from (7.9375, 37.5047) to (12.7, 32.7422)
  arc A8 centre (-7.9375, 32.7422) radius 4.7625 clockwise from (-12.7, 32.7422) to (-7.9375, 37.5047)
  circle C11 centre (22.225, -25.4) radius 3.9687
  circle C12 centre (-22.225, -25.4) radius 3.9688
  circle C13 centre (-22.225, -25.4) radius 3.9688
  circle C14 centre (22.225, 25.4) radius 3.9687
  circle C15 centre (22.225, 25.4) radius 3.9687
  circle C16 centre (-22.225, 25.4) radius 3.9687
  circle C17 centre (-22.225, 25.4) radius 3.9687
  circle C18 centre (0, 0) radius 6.35
  point P48 (28.575, -38.1)
  point P52 (28.575, -38.1)
  point P49 (-28.575, 38.1)
  point P50 (-28.575, 38.1)
  point P58 (-28.575, 0)
  point P59 (28.575, 0)
  point P60 (0, 38.1)
  point P61 (0, -38.1)
  point P62 (0, 0)
  horizontal L17
  vertical L18
  horizontal L19
  vertical L20
  coincident P48 P52
  coincident P49 P50
  midpoint L5 P58
  midpoint L18 P59
  midpoint L17 P60
  midpoint L19 P61
  midpoint L24 P62
  dimension "d123" diameter C18 = 12.7
extrude "Extrude1" new body sketch "Sketch1" profile of L3 L7 L17 L19 L21 L22 C18 against normal blind 2.54
extrude "Extrude2" add sketch "Sketch1" profile of L1 L2 L3 L4 L5 L6 L7 L8 C1 C2 C3 C4 C5 C6 C11 C12 C13 C14 C15 C16 C17 L17 L18 L19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 along normal blind 10.16
extrude "Extrude3" cut sketch "Sketch1" profile of C3 C4 C5 C6 C11 C12 C13 C14 C15 C16 C17 along normal blind 2.032
extrude "Extrude4" sketch "Sketch1" profile of C3 C4 C5 C6 C11 C12 C13 C14 C15 C16 C17 blind -3.9688 (= "( -5 / 32 ) * 1 in")
extrude "Extrude5" add sketch "Sketch1" profile of L1 L2 L8 L21 along normal blind 10.16
base_feature "Base Feature1"
position "Position4"
copy_paste_bodies "CopyPasteBodies1"
move "Move1"
copy_paste_bodies "CopyPasteBodies2"
move "Move2"
copy_paste_bodies "CopyPasteBodies3"
move "Move3"
align "Align1"
align "Align2"
align "Align3"
align "Align4"
position "Position5"
remove_body "RemoveBody1"
sketch "Sketch1" plane through (28.575, 0, 0) normal (1, 0, 0) x axis (0, 1, 0)
  line L1 (38.1, 0) -> (-38.1, 0)
  line L2 (38.1, 127) -> (38.1, 0)
  line L3 (-38.1, 127) -> (38.1, 127)
  line L4 (-38.1, 0) -> (-38.1, 127)
  circle C1 centre (0, 38.1) radius 5.8674
  circle C2 centre (0, 38.1) radius 4
  concentric C1 C2
  dimension "d135" diameter C2 = 8
extrude "Extrude1" sketch "Sketch1" profile of C2 blind 77.5
sketch "Sketch1" plane through (0, 0, 0) normal (1, 0, 0) x axis (0, 1, 0)
  line L1 (-11.475, 93.3333) -> (-16.725, 93.3333)
  line L2 (-16.725, 92.5833) -> (-11.475, 92.5833)
  line L3 (-11.475, 101.8) -> (-16.725, 101.8)
  line L4 (-16.725, 101.05) -> (-11.475, 101.05)
  line L5 (-11.475, 110.2667) -> (-16.725, 110.2667)
  line L6 (-16.725, 109.5167) -> (-11.475, 109.5167)
  line L7 (-11.475, 112.3833) -> (-16.725, 112.3833)
  line L8 (-16.725, 111.6333) -> (-11.475, 111.6333)
  line L9 (-11.475, 103.9167) -> (-16.725, 103.9167)
  line L10 (-16.725, 103.1667) -> (-11.475, 103.1667)
  line L11 (-11.475, 95.45) -> (-16.725, 95.45)
  line L12 (-16.725, 94.7) -> (-11.475, 94.7)
  line L13 (-11.475, 91.2167) -> (-16.725, 91.2167)
  line L14 (-16.725, 90.4667) -> (-11.475, 90.4667)
  line L15 (-11.475, 99.6833) -> (-16.725, 99.6833)
  line L16 (-16.725, 98.9333) -> (-11.475, 98.9333)
  line L17 (-11.475, 108.15) -> (-16.725, 108.15)
  line L18 (-16.725, 107.4) -> (-11.475, 107.4)
  line L19 (-16.725, 113.75) -> (-11.475, 113.75)
  line L20 (-11.475, 114.5) -> (-16.725, 114.5)
  line L21 (-11.475, 106.0333) -> (-16.725, 106.0333)
  line L22 (-16.725, 105.2833) -> (-11.475, 105.2833)
  line L23 (-11.475, 97.5667) -> (-16.725, 97.5667)
  line L24 (-16.725, 96.8167) -> (-11.475, 96.8167)
  line L25 (-11.475, 89.1) -> (-16.725, 89.1)
  line L26 (-16.725, 88.35) -> (-11.475, 88.35)
  line L27 (5.588, 116.84) -> (6.0357, 125.7934)
  line L28 (5.588, 58.2803) -> (5.588, 116.84)
  line L29 (-5.588, 116.84) -> (-5.588, 58.2803)
  line L30 (-6.0357, 125.7934) -> (-5.588, 116.84)
  line L31 (-38.1, 127) -> (-7.3041, 127)
  line L32 (-38.1, 0) -> (-38.1, 127)
  line L33 (38.1, 0) -> (-38.1, 0)
  line L34 (38.1, 127) -> (38.1, 0)
  line L35 (7.3041, 127) -> (38.1, 127)
  line L36 (-20.574, 15.748) -> (-20.574, 93.472)
  line L37 (-31.75, 93.472) -> (-31.75, 15.748)
  line L38 (0, 127) -> (0, 58.2803)
  line L39 (-9.671, 63.5) -> (9.671, 63.5)
  line L40 (-9.671, 101.6) -> (-9.671, 63.5)
  line L41 (9.671, 101.6) -> (-9.671, 101.6)
  line L42 (9.671, 63.5) -> (9.671, 101.6)
  line L43 (-9.671, 101.6) -> (9.671, 63.5)
  line L44 (9.671, 101.6) -> (-9.671, 63.5)
  line L45 (-9.29, 63.881) -> (9.29, 63.881)
  line L46 (-9.29, 101.219) -> (-9.29, 63.881)
  line L47 (9.29, 101.219) -> (-9.29, 101.219)
  line L48 (9.29, 63.881) -> (9.29, 101.219)
  line L49 (9.29, 88.9) -> (9.671, 91.44)
  line L50 (9.29, 63.5) -> (9.29, 88.9)
  line L51 (-9.29, 88.9) -> (-9.671, 91.44)
  line L52 (-9.29, 63.5) -> (-9.29, 88.9)
  line L53 (-5.5245, 64.135) -> (5.5245, 64.135)
  line L54 (-5.5245, 100.965) -> (-5.5245, 64.135)
  line L55 (5.5245, 100.965) -> (-5.5245, 100.965)
  line L56 (5.5245, 64.135) -> (5.5245, 100.965)
  line L57 (-5.5245, 100.965) -> (5.5245, 64.135)
  line L58 (5.5245, 100.965) -> (-5.5245, 64.135)
  line L59 (-0.3048, 95.25) -> (-0.3048, 101.6)
  arc A1 centre (-11.475, 92.9583) radius 0.375 clockwise from (-11.475, 93.3333) to (-11.475, 92.5833)
  arc A2 centre (-16.725, 92.9583) radius 0.375 clockwise from (-16.725, 92.5833) to (-16.725, 93.3333)
  arc A3 centre (-11.475, 101.425) radius 0.375 clockwise from (-11.475, 101.8) to (-11.475, 101.05)
  arc A4 centre (-16.725, 101.425) radius 0.375 clockwise from (-16.725, 101.05) to (-16.725, 101.8)
  arc A5 centre (-11.475, 109.8917) radius 0.375 clockwise from (-11.475, 110.2667) to (-11.475, 109.5167)
  arc A6 centre (-16.725, 109.8917) radius 0.375 clockwise from (-16.725, 109.5167) to (-16.725, 110.2667)
  arc A7 centre (-11.475, 112.0083) radius 0.375 clockwise from (-11.475, 112.3833) to (-11.475, 111.6333)
  arc A8 centre (-16.725, 112.0083) radius 0.375 clockwise from (-16.725, 111.6333) to (-16.725, 112.3833)
  arc A9 centre (-11.475, 103.5417) radius 0.375 clockwise from (-11.475, 103.9167) to (-11.475, 103.1667)
  arc A10 centre (-16.725, 103.5417) radius 0.375 clockwise from (-16.725, 103.1667) to (-16.725, 103.9167)
  arc A11 centre (-11.475, 95.075) radius 0.375 clockwise from (-11.475, 95.45) to (-11.475, 94.7)
  arc A12 centre (-16.725, 95.075) radius 0.375 clockwise from (-16.725, 94.7) to (-16.725, 95.45)
  arc A13 centre (-11.475, 90.8417) radius 0.375 clockwise from (-11.475, 91.2167) to (-11.475, 90.4667)
  arc A14 centre (-16.725, 90.8417) radius 0.375 clockwise from (-16.725, 90.4667) to (-16.725, 91.2167)
  arc A15 centre (-11.475, 99.3083) radius 0.375 clockwise from (-11.475, 99.6833) to (-11.475, 98.9333)
  arc A16 centre (-16.725, 99.3083) radius 0.375 clockwise from (-16.725, 98.9333) to (-16.725, 99.6833)
  arc A17 centre (-11.475, 107.775) radius 0.375 clockwise from (-11.475, 108.15) to (-11.475, 107.4)
  arc A18 centre (-16.725, 107.775) radius 0.375 clockwise from (-16.725, 107.4) to (-16.725, 108.15)
  arc A19 centre (-16.725, 114.125) radius 0.375 clockwise from (-16.725, 113.75) to (-16.725, 114.5)
  arc A20 centre (-11.475, 114.125) radius 0.375 clockwise from (-11.475, 114.5) to (-11.475, 113.75)
  arc A21 centre (-11.475, 105.6583) radius 0.375 clockwise from (-11.475, 106.0333) to (-11.475, 105.2833)
  arc A22 centre (-16.725, 105.6583) radius 0.375 clockwise from (-16.725, 105.2833) to (-16.725, 106.0333)
  arc A23 centre (-11.475, 97.1917) radius 0.375 clockwise from (-11.475, 97.5667) to (-11.475, 96.8167)
  arc A24 centre (-16.725, 97.1917) radius 0.375 clockwise from (-16.725, 96.8167) to (-16.725, 97.5667)
  arc A25 centre (-11.475, 88.725) radius 0.375 clockwise from (-11.475, 89.1) to (-11.475, 88.35)
  arc A26 centre (-16.725, 88.725) radius 0.375 clockwise from (-16.725, 88.35) to (-16.725, 89.1)
  circle C1 centre (0, 38.1) radius 11.049
  arc A27 centre (7.3041, 125.73) radius 1.27 clockwise from (6.0357, 125.7934) to (7.3041, 127)
  arc A28 centre (0, 58.2803) radius 5.588 clockwise from (5.588, 58.2803) to (-5.588, 58.2803)
  arc A29 centre (-7.3041, 125.73) radius 1.27 clockwise from (-7.3041, 127) to (-6.0357, 125.7934)
  arc A30 centre (-26.162, 15.748) radius 5.588 clockwise from (-20.574, 15.748) to (-31.75, 15.748)
  arc A31 centre (-26.162, 93.472) radius 5.588 clockwise from (-31.75, 93.472) to (-20.574, 93.472)
  circle C2 centre (0, 69.6595) radius 3.9687
  circle C3 centre (-5.226, 95.25) radius 2.3813
  circle C4 centre (-5.226, 95.25) radius 4.9213
  circle C5 centre (0, 69.6595) radius 5.5245
  point P87 (0, 58.2803)
  point P102 (0, 58.2803)
  point P108 (0, 82.55)
  point P113 (9.671, 91.44)
  point P114 (9.29, 88.9)
  point P115 (9.29, 63.5)
  point P116 (-9.671, 91.44)
  point P117 (-9.29, 88.9)
  point P118 (-9.29, 63.5)
  point P123 (0, 82.55)
  point P124 (0, 69.6595)
  point P127 (-0.3048, 101.6)
  point P128 (-0.3048, 95.25)
  point P129 (0, 69.6595)
  point P106 (-9.671, 101.6)
  point P107 (9.671, 101.6)
  point P105 (-9.671, 63.5)
  point P121 (-5.5245, 100.965)
  point P122 (5.5245, 100.965)
  point P120 (-5.5245, 64.135)
  point P125 (-5.226, 95.25)
  coincident P87 P102
  vertical L38
  horizontal L39
  perpendicular L39 L40
  parallel L39 L41
  parallel L40 L42
  coincident L43 P108
  coincident L44 P108
  coincident L38 P108
  coincident L42 P113
  coincident L48 P114
  coincident L39 P115
  perpendicular L39 L50
  symmetric L38 P113 P116
  symmetric L38 P114 P117
  symmetric L38 P115 P118
  horizontal L53
  perpendicular L53 L54
  parallel L53 L55
  parallel L54 L56
  coincident L57 P123
  coincident L58 P123
  coincident P108 P123
  coincident L38 P124
  coincident L41 P127
  perpendicular L47 L59
  tangent C4 L59
  coincident C4 P128
  coincident L38 P129
  tangent L53 C5
  coincident P124 P129
  dimension "d139" distance P106 P107 = 19.3421
  dimension "d140" distance P105 P106 = 38.1
  dimension "d141" = 0.381
  dimension "d142" distance L35 L41 = 25.4
  dimension "d143" distance P107 P113 = 10.16
  dimension "d144" distance P107 P114 = 12.7
  dimension "d145" distance P121 P122 = 11.049
  dimension "d146" distance P120 P121 = 36.83
  dimension "d147" diameter C2 = 7.9375
  dimension "d149" diameter C3 = 4.7625
  dimension "d150" distance L40 P125 = 4.445
  dimension "d151" distance L41 P125 = 6.35
  dimension "d152" = 2.54
  dimension "d153" diameter C5 = 11.049
extrude "Extrude1" sketch "Sketch1" profile of L39 L40 L41 L42 L49 L50 L51 L52 L53 L54 L55 L56 C2 C3 C4 L59 C5 to an object bodies "Wheel Block"
extrude "Extrude2" sketch "Sketch1" profile of L54 L55 L56 C2 C4 L59 C5 blind 3.175
extrude "Extrude3" of existing geometry blind -3.175
sketch "Sketch2" plane through (-19.05, 0, 0) normal (-1, 0, 0) x axis (0, -1, 0)
  line L1 (0.3048, 100.965) -> (0.3048, 95.25)
  line L2 (-5.5245, 100.965) -> (0.3048, 100.965)
  line L3 (-5.5245, 69.6595) -> (-5.5245, 100.965)
  line L4 (5.5245, 90.3378) -> (5.5245, 69.6595)
  circle C1 centre (0, 69.6595) radius 3.9687
  arc A1 centre (0, 69.6595) radius 5.5245 clockwise from (5.5245, 69.6595) to (-5.5245, 69.6595)
  arc A2 centre (5.226, 95.25) radius 4.9213 clockwise from (5.5245, 90.3378) to (0.3048, 95.25)
  circle C2 centre (0, 69.6595) radius 3.9688
  circle C3 centre (5.226, 95.25) radius 2.2225
  concentric C1 C2
  concentric A2 C3
  dimension "d163" diameter C2 = 7.9375 (= "( 5 / 16 ) * 1 in")
  dimension "d166" diameter C3 = 4.445
extrude "Extrude4" new body sketch "Sketch2" profile of C1 C2 against normal blind 31.75 bodies "Wheel Pin"
move "Move1"
extrude "Extrude5" sketch "Sketch2" profile of C3 to an object bodies "Locking Pin"
sketch "Sketch3" plane through (0, -9.671, 0) normal (0, -1, 0) x axis (1, 0, 0)
  line L1 (15.875, 101.6) -> (15.875, 91.44)
  line L2 (-15.875, 101.6) -> (15.875, 101.6)
  line L3 (-15.875, 91.44) -> (-15.875, 101.6)
  line L4 (15.875, 91.44) -> (-15.875, 91.44)
  line L5 (-19.05, 64.135) -> (-19.05, 69.6595)
  line L6 (-19.05, 69.6595) -> (-19.05, 100.965)
  line L7 (-19.05, 100.965) -> (-15.875, 100.965)
  line L8 (19.05, 100.965) -> (15.875, 100.965)
  line L9 (19.05, 100.965) -> (19.05, 69.6595)
  line L10 (19.05, 69.6595) -> (19.05, 64.135)
  line L11 (15.875, 64.135) -> (15.875, 63.5)
  line L12 (15.875, 63.5) -> (-15.875, 63.5)
  line L13 (-15.875, 63.5) -> (-15.875, 64.135)
  line L14 (15.875, 101.6) -> (-15.875, 101.6)
  line L15 (15.875, 101.6) -> (15.875, 100.965)
  line L16 (-15.875, 100.965) -> (-15.875, 101.6)
  line L17 (-19.05, 64.135) -> (-15.875, 64.135)
  line L18 (19.05, 64.135) -> (15.875, 64.135)
  line L19 (0, 63.5) -> (0, 101.6)
  line L20 (-5.3086, 57.15) -> (5.3086, 57.15)
  line L21 (-5.3086, 107.95) -> (-5.3086, 57.15)
  line L22 (5.3086, 107.95) -> (-5.3086, 107.95)
  line L23 (5.3086, 57.15) -> (5.3086, 107.95)
  line L24 (-5.3086, 107.95) -> (5.3086, 57.15)
  line L25 (5.3086, 107.95) -> (-5.3086, 57.15)
  line L26 (19.05, 88.9) -> (-19.05, 88.9)
  circle C1 centre (0, 83.5914) radius 5.3086
  point P20 (0, 101.6)
  point P21 (0, 63.5)
  point P26 (0, 82.55)
  point P27 (0, 83.5914)
  point P28 (-19.05, 88.9)
  point P29 (19.05, 88.9)
  point P24 (-5.3086, 107.95)
  point P25 (5.3086, 107.95)
  point P23 (-5.3086, 57.15)
  midpoint L14 P20
  midpoint L12 P21
  horizontal L20
  perpendicular L20 L21
  parallel L20 L22
  parallel L21 L23
  coincident L24 P26
  coincident L25 P26
  midpoint L19 P26
  coincident L19 P27
  coincident L6 P28
  coincident L9 P29
  perpendicular L9 L26
  tangent C1 L26
  dimension "d170" distance P24 P25 = 10.6172
  dimension "d171" distance P23 P24 = 50.8
  dimension "d172" diameter C1 = 10.6172
  dimension "d173" distance L14 L26 = 12.7
extrude "Extrude6" cut sketch "Sketch3" profile of L12 L21 L23 C1 against normal blind 19.3548
fillet "Fillet1" radius 3.175
fillet "Fillet2" radius 1.27
extrude "Extrude7" cut sketch "Sketch1" profile of C18 against normal blind 40.64
extrude "Extrude8" sketch "Sketch1" profile of C18 blind 76.2 bodies "Wheel Screw"
thread "Thread1"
